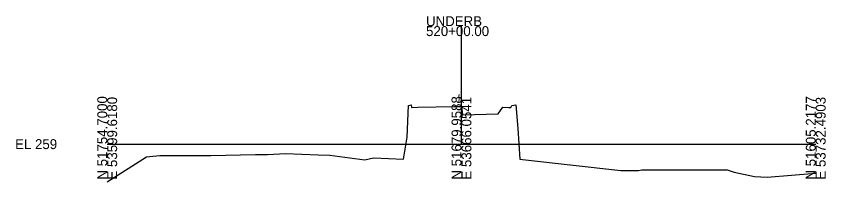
# Model space of a CAD drawing. Extents: x 12366 to 12594, y 96215 to 101752.
# Drawn here: x 12365.6 to 12594.1, y 98714 to 98760.7 of the extents above; entities that cross this region are included whole.
import ezdxf

# ---------------------------------------------------------------- set-up
doc = ezdxf.new("R2010")
doc.units = 0
for name, color, linetype in [('Level 10', 7, 'Continuous'), ('Level 60', 7, 'Continuous'), ('Level 63', 7, 'Continuous')]:
    doc.layers.add(name, color=color, linetype=linetype)

msp = doc.modelspace()

# ---------------------------------------------------------------- linework, layer by layer
at = {"layer": 'Level 60'}
for p, q in [((12475.96, 98726.64), (12476.38, 98735.53)), ((12476.38, 98735.53), (12477.08, 98735.68)), ((12477.08, 98735.68), (12477.24, 98734.96)), ((12477.24, 98734.96), (12479.02, 98735.05)), ((12479.02, 98735.05), (12489.2, 98735.25)), ((12489.2, 98735.25), (12491.35, 98735.29)), ((12491.35, 98735.29), (12491.57, 98732.91)), ((12501.7, 98733.15), (12502.94, 98735.08)), ((12502.94, 98735.08), (12504.71, 98734.99)), ((12504.71, 98734.99), (12505.27, 98734.97)), ((12505.27, 98734.97), (12505.47, 98735.56)), ((12505.47, 98735.56), (12506.64, 98735.73)), ((12506.64, 98735.73), (12507.25, 98729.03)), ((12491.57, 98732.91), (12501.7, 98733.15)), ((12507.25, 98729.03), (12507.79, 98720.42)), ((12474.9, 98720.44), (12475.96, 98726.64)), ((12391.3, 98714.02), (12402.38, 98721.06)), ((12402.38, 98721.06), (12403.22, 98721.19)), ((12403.22, 98721.19), (12406.18, 98721.41)), ((12406.18, 98721.41), (12420.58, 98721.46)), ((12420.58, 98721.46), (12433.18, 98721.67)), ((12433.18, 98721.67), (12436.53, 98721.76)), ((12436.53, 98721.76), (12441.61, 98721.99)), ((12441.61, 98721.99), (12450.86, 98721.65)), ((12450.86, 98721.65), (12454.12, 98721.56)), ((12454.12, 98721.56), (12464.05, 98720.22)), ((12464.05, 98720.22), (12466.51, 98720.8)), ((12466.51, 98720.8), (12474.9, 98720.44)), ((12507.79, 98720.42), (12508.56, 98720.28)), ((12508.56, 98720.28), (12536.3, 98717.22)), ((12536.3, 98717.22), (12541.29, 98717.2)), ((12541.29, 98717.2), (12542.24, 98717.38)), ((12542.24, 98717.38), (12548.05, 98717.38)), ((12548.05, 98717.38), (12566.3, 98717.36)), ((12566.3, 98717.36), (12568.25, 98716.73)), ((12568.25, 98716.73), (12574.02, 98715.5)), ((12574.02, 98715.5), (12577.59, 98715.28)), ((12577.59, 98715.28), (12591.3, 98716.45))]:
    msp.add_line(p, q, dxfattribs=at)
at = {"layer": 'Level 63'}
for p, q in [((12491.3, 98724.64), (12491.3, 98757.91)), ((12391.3, 98724.64), (12491.3, 98724.64)), ((12491.3, 98724.64), (12591.3, 98724.64))]:
    msp.add_line(p, q, dxfattribs=at)

# ---------------------------------------------------------------- texts
at = {"layer": 'Level 10'}
msp.add_text('269.65', height=0.6, rotation=90, dxfattribs=at).set_placement((12490.9, 98736.29))
at = {"layer": 'Level 63'}
for s, p in [('UNDERB', (12481.3, 98757.91)), ('520+00.00', (12481.3, 98755.11)), ('EL 259', (12365.3, 98723.24))]:
    msp.add_text(s, height=2.8, dxfattribs=at).set_placement(p)
for s, p in [('N 51754.7000', (12391.3, 98714.64)), ('E 53599.6180', (12394.1, 98714.64)), ('N 51679.9588', (12491.3, 98714.64)), ('E 53666.0541', (12494.1, 98714.64)), ('N 51605.2177', (12591.3, 98714.64)), ('E 53732.4903', (12594.1, 98714.64))]:
    msp.add_text(s, height=2.8, rotation=90, dxfattribs=at).set_placement(p)

doc.saveas('drawing.dxf')
